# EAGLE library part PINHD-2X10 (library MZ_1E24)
PIN HEADER
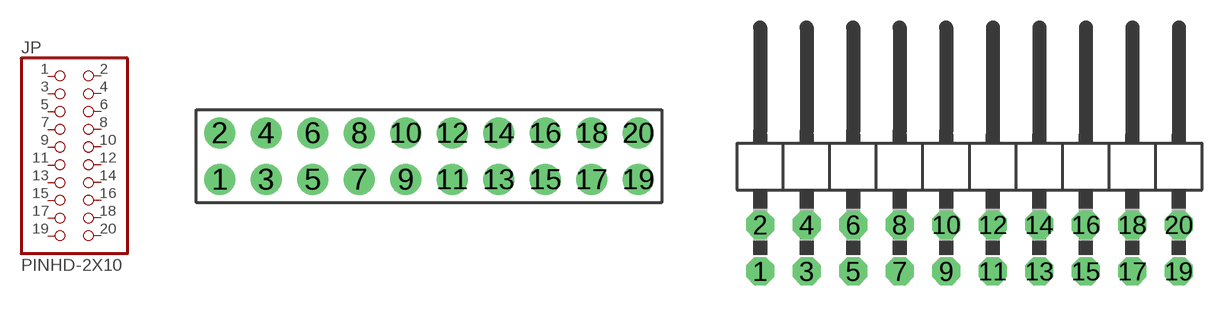
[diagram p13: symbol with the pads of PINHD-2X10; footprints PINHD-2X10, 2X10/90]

Designator prefix JP

## PINHD-2X10  [PINHD-2X10]
1  1  pas
2  2  pas
3  3  pas
4  4  pas
5  5  pas
6  6  pas
7  7  pas
8  8  pas
9  9  pas
10  10  pas
11  11  pas
12  12  pas
13  13  pas
14  14  pas
15  15  pas
16  16  pas
17  17  pas
18  18  pas
19  19  pas
20  20  pas

## PINHD-2X10/90  [2X10/90]
Pads as for PINHD-2X10

## PINHD-2X10A  [PINHD-2X10A]
Pads as for PINHD-2X10

## Footprint PINHD-2X10 (pad centres in mm)
PIN HEADER
drill 1.016 pad 1.676 round: 1 -11.43,-1.27; 2 -11.43,1.27; 3 -8.89,-1.27; 4 -8.89,1.27; 5 -6.35,-1.27; 6 -6.35,1.27; 7 -3.81,-1.27; 8 -3.81,1.27; 9 -1.27,-1.27; 10 -1.27,1.27; 11 1.27,-1.27; 12 1.27,1.27; 13 3.81,-1.27; 14 3.81,1.27; 15 6.35,-1.27; 16 6.35,1.27; 17 8.89,-1.27; 18 8.89,1.27; 19 11.43,-1.27; 20 11.43,1.27

## Footprint 2X10/90 (pad centres in mm)
PIN HEADER
drill 1.016 octagon: 1 -11.43,-6.35; 2 -11.43,-3.81; 3 -8.89,-6.35; 4 -8.89,-3.81; 5 -6.35,-6.35; 6 -6.35,-3.81; 7 -3.81,-6.35; 8 -3.81,-3.81; 9 -1.27,-6.35; 10 -1.27,-3.81; 11 1.27,-6.35; 12 1.27,-3.81; 13 3.81,-6.35; 14 3.81,-3.81; 15 6.35,-6.35; 16 6.35,-3.81; 17 8.89,-6.35; 18 8.89,-3.81; 19 11.43,-6.35; 20 11.43,-3.81

## Footprint PINHD-2X10A (pad centres in mm)
drill 1.016 pad 1.676 round: 1 -11.43,-1.27; 2 -11.43,1.27; 3 -8.89,-1.27; 4 -8.89,1.27; 5 -6.35,-1.27; 6 -6.35,1.27; 7 -3.81,-1.27; 8 -3.81,1.27; 9 -1.27,-1.27; 10 -1.27,1.27; 11 1.27,-1.27; 12 1.27,1.27; 13 3.81,-1.27; 14 3.81,1.27; 15 6.35,-1.27; 16 6.35,1.27; 17 8.89,-1.27; 18 8.89,1.27; 19 11.43,-1.27; 20 11.43,1.27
